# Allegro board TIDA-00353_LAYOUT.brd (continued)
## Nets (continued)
N17161357: C222.1 U10.1(BYPASS)
N17161563: C233.1 C234.1 R177.2 R180.1 U11.5(OUT) Z11.1 Z12.1 Z13.1
N17161629: R175.2 R176.1 U11.8(S\D\)
N17161669: C233.2 R177.1 R178.1 U11.6(ADJ)
N17161679: C232.1 U11.1(BYPASS)
N17161879: C204.1 C205.1 R162.2 U8.5(OUT) Z4.1 Z6.1
N17161936: C200.2 R160.2 R161.2 R235.2 U8.8(S\D\)
N17162041: C214.1 C215.1 R166.2 U9.5(OUT) Z7.1
N17162051: C210.2 R164.2 R165.2 R236.2 U9.8(S\D\)
N17162120: C215.2 R166.1 R167.1 U9.6(ADJ)
N17162132: C213.1 U9.1(BYPASS)
N17162350: C205.2 R162.1 R163.1 U8.6(ADJ)
N17162360: C203.1 U8.1(BYPASS)
N17167261: LMKSPI.2(E) R147.2
N17167267: LMKSPI.4(F) R149.2
N17167273: LMKSPI.8(H) R151.2
N17204057: C162.1 R103.2 Y3.1(VTUNE)
N17204061: C160.1 C161.1 R103.1 U13.32(CPOUT1)
N17204110: REFCLK.1(CENTER) T5.1
N17204122: C149.1 U13.12(LDOBYP2)
N17204150: R110.2 Y1.4(RF) Y2.3(OUT)
N17204206: C148.1 U13.11(LDOBYP1)
N17204360: EXTREF.1(CENTER) R107.2 R108.1
N17204562: C150.1 C151.1 U13.46(CPOUT2)
N17204592: C150.2 R100.1
N17204632: R102.2 Y3.4(RF)
N17204638: C158.2 R101.2 R102.1
N17204674: C168.1 R111.2 R112.1 Y1.1(VTUNE) Y2.1(EN)
N17204744: C152.1 U13.44(OSCIN*)
N17243114: FMC.H37 R65.1
N17243121: FMC.H38 R66.1
N17243521: FMC.G36 R63.2
N17243524: FMC.G37 R64.2
N17262131: BP2.5.1 C96.1 C97.2 C98.1 U12.41(BP2.5_41)
N17267182: C147.2 R96.2 R97.2 R99.1 U13.6(SYNC)
N17394464: Q4.3(D) SYNC.2(CATHODE)
N17403168: OVRA/TRIGRDY.1(ANODE) R58.1
N17405429: OVRB/TRIGGER.1(ANODE) R57.1
N17407540: Q2.1(G) R53.1 R56.2 U12.44(OVRA/TRIGRDY)
N17407548: Q3.1(G) R54.1 R55.2 U12.43(OVRB/TRIGGER)
N17461045: STATUS_LD2.1 U13.48(STATUS_LD2)
N17467440: C153.2 C155.2 C157.2 C158.1 C159.2
N17467450: C153.1 U13.43(OSCIN)
N17467802: C156.1 U13.35(CLKIN1*/FIN*/FBCLKIN*)
N17467807: C157.1 U13.34(CLKIN1/FIN/FBCLKIN)
N17467978: C154.1 U13.38(CLKIN0*)
N17467983: C155.1 U13.37(CLKIN0)
N17471425: STATUS_LD1.1 U13.31(STATUS_LD1)
N17477944: CLKIN_SEL1.1 U13.59(CLKIN_SEL1)
N17492975: C146.2 R94.2 R95.2 R98.1 U13.5(RESET)
N17497915: LMK_RESET.2 R94.1
N17498425: LMK_SYNC.2 R97.1
N17498929: FMC.H31 Q4.1(G) R67.1
N17500015: FMC.D31 R62.1
N17500071: FMC.D30 R62.2
N17502672: R168.2 R169.1 U10.8(S\D\)
N17525558: CLKIN_SEL0.1 U13.58(CLKIN_SEL0)
N17567551: C113.2 R51.2 R52.1 SYSREF_SW.2
N17588026: L1.1 R36.2 U3.24(OPA+)
N17588195: C21.2 T9.3
N17588197: C20.2 T9.1
N17588243: R34.2 U3.22(ENA)
N17588312: R30.1 R31.1 U3.4(MOD0)
N17588326: R32.1 R33.1 U3.5(MOD1)
N17588682: C21.1 U3.30(IPA+)
N17588716: C20.1 U3.29(IPA-)
N17588832: L2.1 R37.2 U3.23(OPA-)
N17588912: L4.2 R38.2 U3.18(OPB-)
N17589096: C22.1 U3.11(IPB+)
N17589248: C23.1 U3.12(IPB-)
N17589348: R35.2 U3.19(ENB)
N17589483: C23.2 T8.3
N17591143: L3.2 R39.2 U3.17(OPB+)
N17597838: R119.1 R120.2 Z1.3
N17597840: C183.1 R119.2 U6.20(VCC)
N17597844: C180.1 R120.1 U7.4(EN) U7.6(VIN)
N17597872: C181.1 U7.1(VOUT) Z3.1
N17597980: R126.1 U6.1(D0)
N17597982: R127.1 U6.5(D1)
N17597984: R128.1 U6.3(D2)
N17597986: R129.1 U6.11(D3)
N17597988: R130.1 U6.2(D4)
N17597998: R131.1 U6.9(D5)
N17598000: R132.1 U6.10(D6)
N17598002: R133.1 U6.6(D7)
N17599264: C185.1 U6.16(USBDM) USB.2(D-)
N17599267: C186.1 U6.15(USBDP) USB.3(D+)
N17600241: USB.1(VBUS) Z1.1
N17600317: C187.1 U6.17(3V3OUT)
N17600450: R121.1 U6.12(P\W\R\E\N\)
N17601684: R134.1 U14.3(A1)
N17602039: R138.1 U15.3(A1)
N17602344: R141.1 U16.3(A1)
N17602346: R142.1 U16.4(A2)
N17602348: R143.1 U16.5(A3)
N17602350: R144.1 U16.6(A4)
N17603643: R135.1 U14.4(A2)
N17603676: R136.1 U14.5(A3)
N17603709: R137.1 U14.6(A4)
N17603775: R139.1 U15.4(A2)
N17603808: R140.1 U15.5(A3)
N17607444: JP2.2 R159.1 U16.9(OEB)
N17608737: J1.4 R17.2 U3.31(A1/SDO/S0A)
N17692169: C2.2 T2.4
N17692215: R2.1 T1.4 VINA-.1(CENTER)
N17692227: C1.1 T1.1
N17692229: C2.1 T1.3
N17692231: R1.2 R3.1 T1.6 VINA+.1(CENTER)
N17692255: R5.2 R6.2 T7.4 VINB+.1(CENTER)
N17692293: C5.2 T6.4
N17692319: C6.1 T7.2
N17692331: C4.2 T6.6
N17692399: C1.2 T2.6
N17692405: C9.1 C10.1 R7.2 R10.2 R11.2 R16.1 VCMA.1
N17692416: R8.1 R10.1 R12.2 R14.1
N17692426: C7.1 R7.1 T2.2
N17692454: R4.2 T7.6 VINB-.1(CENTER)
N17692538: C11.1 C12.1 R22.2 R23.2 R26.2 R27.1 VCMB.1
N17692596: C5.1 T7.3
N17692598: C4.1 T7.1
N17692610: R9.1 R11.1 R13.2 R15.1
N17692612: C8.1 R26.1 T6.2
N17692676: C3.1 T1.2
N17695733: C40.1 L6.1
N17695767: C41.1 L7.1
N17701277: C22.2 T8.1
N17703127: R20.1 R22.1 R24.2 R28.2
N17703165: R21.1 R23.1 R25.2 R29.2
N17704949: C46.1 L10.1
N17704975: C47.1 L11.1
N17708763: R73.1 T3.3
N17708767: R72.1 T3.1
N17709160: R78.1 T4.1
N17709162: R79.1 T4.3
N17709444: CLK.1(CENTER) R70.1 R220.1
N17709615: R71.1 SYSREF.1(CENTER) T4.6
N17746469: C28.2 R36.1
N17746475: C29.2 R37.1
N17746481: C30.2 R38.1
N17746487: C31.2 R39.1
N17748434: R181.2 UNK+5V.1 Z17.1
N17896945: LMKSPI.6(G) R145.1
N17897426: LMKSPI.9(I) R40.2
N17899231: LMKSPI.7(D) R152.1
N17899957: LMKSPI.1(A) R156.1
N17947980: C195.2 JP1.2(PIN2) U14.16(VCCA)
N18004813: R217.2 R219.2 R221.2
N18004844: R220.2 R221.1 T3.6
N18006132: C120.2 T3.2 T3.5
N18006814: C121.2 T4.2 T4.5
N172049681: C161.2 R104.1
N173478561: OVRA/TRIGRDY.2(CATHODE) Q2.3(D)
N173944760: R68.2 SYNC.1(ANODE)
N174054101: OVRB/TRIGGER.2(CATHODE) Q3.3(D)

Pads without a net: FMC A14 A15 A18 A19 A22 A23 A26 A27 A30 A31 A34 A35 A38 A39 B1 B4 B5 B8 B9 B12 B13 B16 B17 B20 B21 B24 B25 B28 B29 B32 B33 B36 B37 B40 C2 C3 C10 C11 C14 C15 C18 C19 C22 C23 C26 C27 C30 C31 C34 C35 C37 C39 D14 D15 D17 D18 D20 D21 D23 D24 D27 D29 D32 D33 D34 D35 D36 D38 D40 E2 E3 E6 E7 E9 E10 E12 E13 E15 E16 E18 E19 E21 E22 E24 E25 E27 E28 E30 E31 E33 E34 E36 E37 F4 F5 F7 F8 F10 F11 F13 F14 F16 F17 F19 F20 F22 F23 F25 F26 F28 F29 F31 F32 F34 F35 F37 F38 G2 G3 G15 G16 G18 G19 G21 G22 G24 G25 G28 G30 G31 G33 G34 H1 H4 H5 H7 H8 H10 H11 H13 H14 H16 H17 H19 H20 H22 H23 H25 H26 H28 H29 H32 H34 H35 J2 J3 J6 J7 J9 J10 J12 J13 J15 J16 J18 J19 J21 J22 J24 J25 J27 J28 J30 J31 J33 J34 J36 J37 K1 K4 K5 K7 K8 K10 K11 K13 K14 K16 K17 K19 K20 K22 K23 K25 K26 K28 K29 K31 K32 K34 K35 K37 K38; LMKSPI 3 5 10; MT1 1; MT2 1; MT3 1; MT4 1; MT5 1; MT6 1; T1 5; T2 5; T6 5; T7 5; T8 5; T9 5; U6 8 13 14 19 22 23 24 27 28; U7 2 5; U8 2 7; U9 2 7; U10 2 7; U11 2 7; U13 1 2 3 4 7 8 9 22 23 27 28 29 30 40 41 49 50 60 61 62 63; U15 6; USB 4; Y1 2 5; Y3 2 5

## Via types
v1: diameter 0.406, hole 0.305, TOP to BOTTOM, 934 vias
v2: diameter 0.559, hole 0.305, TOP to BOTTOM, 1408 vias
v3: diameter 0.508, hole 0.203, TOP to BOTTOM, 46 vias

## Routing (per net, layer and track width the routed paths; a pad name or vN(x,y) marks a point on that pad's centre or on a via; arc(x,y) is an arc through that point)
+4V: length 36
  TOP w0.254: U9.4 v1(29.82,34.35) C212.1 ; U10.4 v1(29.44,47.43) v1(28.43,47.43)
  TOP w0.305: U11.4 v1(101.31,17.4) C231.1 ; C202.1 U8.4
  TOP w0.559: 99.19,11.1 98.68,11.1 ; 99.19,11.1 v2(99.19,11.45) v2(98.17,11.45) v2(98.17,10.75) v2(99.19,10.75) 99.19,11.1 ; 38.28,52.38 38.28,52.21 ; 38.28,52.38 v2(37.92,52.38) v2(37.92,51.7) v2(38.63,51.7) v2(38.63,52.38) 38.28,52.38
  TOP w0.762: 38.28,52.21 R179.2 ; 98.68,11.1 R180.2
  TOP w1.27: C230.1 C231.1 ; C211.1 C212.1 ; C220.1 C221.1
  BOTTOM w0.203: v1(101.31,17.4) 104.45,17.4 105.33,16.52 v1(105.33,14.27)
  BOTTOM w0.559: 7.62,32.61 7.62,32.11 ; 7.62,32.11 v2(7.97,32.11) v2(7.97,33.12) v2(7.27,33.12) v2(7.27,32.11) 7.62,32.11
  BOTTOM w0.762: R181.1 7.62,32.61
  vias: v1(25.27,47.43) v1(25.27,46.53) v1(25.65,34.8) v1(25.65,33.9) v1(25.84,47.43) v1(25.84,46.53) v1(26.22,34.8) v1(26.22,33.9) v1(27.76,47.43) v1(27.76,46.53) v1(28.14,34.8) v1(28.14,33.9) v1(28.43,46.53) v1(28.81,34.8) v1(28.81,33.9) v1(32.45,51.44) v1(32.82,38.1) v1(75.89,106.38) v1(75.89,105.16) v1(76.59,106.38) v1(76.59,105.16) v1(80.47,101.42) v1(100.83,21.54) v1(100.83,20.83) v1(100.96,19.26) v1(100.96,18.04) v1(101.67,19.26) v1(101.67,18.04) v1(101.8,21.54) v1(101.8,20.83)
GND: length 300.9
  TOP w0.203: v1(63.23,66.93) 63.23,68 U12.22 ; U12.40 67.77,73.94 v1(67.8,73.91) ; C90.1 70.31,67.82 v1(70.49,68) ; v1(118.34,91.06) 118.55,91.26 118.85,91.26 ; U12.16 v1(60.22,66.93) ; C112.2 65.06,64.34 v2(65.08,64.36) ; C6.2 v1(19.58,58.31) ; C3.2 v1(19.58,85.08)
  TOP w0.254: U11.3 102.11,14.92 v2(102.51,14.92) ; U8.3 77.04,102.04 v2(77.44,102.04) ; U10.3 31.42,48.23 v2(31.82,48.63) ; U9.3 31.8,35.15 v2(32.2,35.55)
  TOP w0.305: U12.12 v1(58.04,69.44) ; U12.46 v1(64.72,76.58) 64.72,77.27 C62.2 ; U12.9 v1(58.15,70.94) ; U12.6 v1(58.15,72.44) ; U12.3 v1(58.18,73.94) ; U12.49 63.22,76.83 63.58,77.19 C65.2 ; U12.31 v1(67.95,69.44) ; U12.52 v1(61.72,76.45) 61.72,76.87 61.47,77.11 C69.2 ; U12.19 v1(61.72,66.93) ; U12.55 v1(60.22,76.7) 60.41,76.89 C67.2 ; U12.25 v1(64.72,66.96)
  TOP w0.33: C88.2 64.92,66.76 v1(64.72,66.96) ; C82.2 60.19,66.9 v1(60.22,66.93)
  TOP w0.381: v1(64.88,79.12) 64.62,78.87 C61.2 64.62,78.11 v1(64.88,77.85) 64.65,77.62 C62.2 ; R67.2 106.56,60.94 v2(106.35,60.73) ; C67.2 60.41,77.62 v1(60.18,77.85) 60.43,78.11 C66.2 60.43,78.87 v1(60.18,79.12) ; v1(58.04,69.44) 57.94,69.34 C77.1 ; R5.1 R4.1 ; v1(68.97,69.32) C93.2 68.08,69.32 v1(67.95,69.44) ; v1(58.15,70.94) 58.12,70.97 C74.1 ; C154.2 v2(91.14,44) ; C152.2 v2(91.14,47) ; v2(75.09,39.88) R92.1 R93.1 v2(75.09,42.11) R90.1 R91.1 v2(75.09,44.35) ; C96.2 v1(70.21,74.42) ; v1(70.08,75.18) C94.1 ; C80.2 61.8,66.85 v1(61.72,66.93) ; C85.2 63.15,66.85 v1(63.23,66.93) ; v1(63.86,79.12) C64.2 v1(63.86,77.85) 63.58,77.57 C65.2 ; v1(58.15,72.44) 58.12,72.42 C73.1 ; C71.2 57.89,74.04 57.99,73.94 v1(58.18,73.94) ; C117.2 v1(56.04,67.56) ; v1(56.14,75.95) C114.2 ; C69.2 61.47,77.6 v1(61.19,77.88) C68.2 v1(61.19,79.12) ; C156.2 v2(91.14,42.5)
  TOP w0.406: C92.2 v1(71.36,68.95) ; R4.1 v2(11.51,58.7) ; R5.1 v2(11.51,57.91) ; v2(11.51,85.47) R1.1 R2.2 v2(11.51,84.69)
  TOP w0.508: v2(105.14,101.09) R60.2 ; v2(9.34,72.66) 9.54,72.46 R32.2 ; R31.2 9.54,70.93 v2(9.34,70.73)
  TOP w0.559: C169.2 v2(95.76,57.62)
  BOTTOM w0.203: U15.11 23.08,30.77 v2(23.73,30.12) ; U14.7 v2(55.35,26.23) ; U14.1 v2(55.35,30.13) 54.7,29.48 U14.2 ; v1(64.72,76.58) 65.33,76.58 C60.1 ; U15.9 24.38,30.77 v2(23.73,30.12) ; v2(23.73,30.12) U15.10 v2(23.73,32.61) ; C75.1 58.15,70.99 v1(58.15,70.94) 57.84,70.64 C76.1 ; U16.2 54.65,23.03 v2(55.3,23.68) U16.1 ; U14.9 47.56,25.58 v2(46.91,26.23) U14.10 ; U15.7 v2(23.73,38.56) 24.03,38.56 24.38,38.21 U15.8 ; U15.2 20.48,38.12 20.04,38.56 v2(19.83,38.56) U15.1 ; C89.1 67.19,66.9 v1(67.16,66.88) ; U16.10 v2(49.35,19.78) ; v2(54.05,18.47) U16.8 ; C63.1 62.39,76.45 v1(61.72,76.45)
  BOTTOM w0.254: U3.15 15.49,74.48 v1(15.74,74.73) 15.99,74.47 15.99,74.1 U3.16 ; U3.20 17.27,71.94 v2(17.52,71.69) 17.27,71.44 U3.21 ; U3.10 12.99,75.59 v2(12.79,75.78) ; U3.25 15.99,69.29 15.99,68.91 v1(15.74,68.66) 15.49,68.91 U3.26 ; v1(14.56,75.67) 14.49,75.61 U3.13 ; U3.3 9.55,70.94 v2(9.34,70.73) ; U3.7 10.35,72.94 v2(10.15,73.14) ; v2(9.34,72.66) 9.55,72.44 U3.6 ; v2(12.31,74.97) 12.49,74.79 U3.9 ; v2(10.97,73.62) 11.15,73.44 U3.8 ; v1(14.56,67.71) 14.49,67.78 U3.28
  BOTTOM w0.33: v1(60.22,66.93) 60.19,66.9 C79.2 ; C86.1 64.9,66.38 C87.2 64.89,66.79 v1(64.72,66.96)
  BOTTOM w0.381: FMC.J8 v1(113.26,89.79) ; FMC.H33 v1(114.53,58.04) ; FMC.F39 v1(117.07,50.42) ; FMC.G35 v1(115.8,55.5) ; FMC.E23 v1(118.34,70.74) ; FMC.H21 v1(114.53,73.28) ; FMC.A29 v1(123.42,63.12) ; FMC.D28 v1(119.61,64.39) ; FMC.J40 v1(113.26,47.88) ; FMC.F24 v1(117.07,69.47) ; FMC.C40 v1(120.88,49.15) ; FMC.J20 v1(113.26,73.28) ; FMC.A13 v1(123.42,82.17) ; FMC.A4 v1(124.69,93.6) ; FMC.K15 v1(113.26,80.9) ; FMC.G29 v1(115.8,63.12) ; FMC.H12 v1(114.53,83.44) ; FMC.E35 v1(118.34,55.5) ; FMC.D19 v1(119.61,75.82) ; FMC.B23 v1(122.15,70.74) ; FMC.D2 v1(120.88,96.14) ; FMC.C16 v1(122.15,78.36) ; C70.2 58.08,74.04 v1(58.18,73.94) ; v1(63.23,66.93) 62.94,66.64 C84.2 ; FMC.B31 v1(122.15,60.58) ; FMC.A37 v1(123.42,52.96) ; v1(61.72,66.93) 61.44,66.64 C81.2 ; FMC.A1 v1(123.42,98.68) ; FMC.C29 v1(120.88,63.12) ; FMC.C9 v1(122.15,88.52) FMC.C8 v1(122.15,89.79) FMC.B7 ; FMC.E17 v1(118.34,78.36) ; FMC.E40 v1(118.34,47.88) ; FMC.H27 v1(114.53,65.66) ; FMC.G38 v1(115.8,50.42) ; C95.1 v1(70.08,75.18) ; FMC.D3 v1(119.61,96.14) ; FMC.E1 v1(118.34,98.68) ; FMC.K9 v1(113.26,87.25) ; v1(114.53,87.25) FMC.H9 FMC.G8 ; FMC.J1 v1(113.26,98.68) ; FMC.F21 v1(117.07,73.28) ; FMC.A36 v1(123.42,54.23) ; v1(118.34,87.25) FMC.F9 FMC.E8 ; FMC.D6 120.05,91.69 v1(119.41,91.06) 120.05,90.42 FMC.D7 ; FMC.B34 v1(122.15,56.77) ; FMC.K24 v1(111.99,69.47) ; FMC.G11 v1(115.8,85.98) ; FMC.D13 v1(120.88,83.44) FMC.C13 ; C72.1 58.12,72.42 v1(58.15,72.44) ; FMC.A17 v1(123.42,78.36) ; FMC.J29 v1(113.26,63.12) ; FMC.G23 v1(115.8,70.74) ; FMC.K36 v1(111.99,54.23) ; FMC.E20 v1(118.34,73.28) ; FMC.B2 v1(122.15,96.14) FMC.B3 ; FMC.G17 v1(115.8,78.36) ; FMC.A5 v1(123.42,93.6) ; FMC.C28 v1(120.88,64.39) ; FMC.K18 v1(113.26,75.82) ; v1(58.04,69.44) 57.94,69.34 C78.1 ; FMC.H18 v1(115.8,75.82) ; FMC.D10 v1(120.88,85.98) ; FMC.D16 v1(119.61,78.36) ; FMC.J5 v1(113.26,93.6) ; FMC.B6 v1(122.15,91.06) ; FMC.F3 v1(117.07,96.14) ; FMC.K33 v1(111.99,58.04) ; FMC.H6 v1(114.53,92.33) ; FMC.B14 v1(122.15,82.17) ; FMC.C25 v1(120.88,68.2) ; FMC.B15 v1(123.42,80.9) ; FMC.K21 v1(111.99,73.28) ; FMC.A32 v1(123.42,59.31) ; v1(30.84,77.38) v1(30.84,78.27) ; FMC.A24 v1(123.42,69.47) ; FMC.E4 v1(118.34,94.87) ; FMC.B39 v1(122.15,50.42) ; FMC.J11 v1(113.26,85.98) ; FMC.H15 v1(114.53,80.9) FMC.J14 ; FMC.K30 v1(111.99,61.85) ; FMC.K12 v1(113.26,83.44) ; FMC.H36 v1(114.53,54.23) ; FMC.D37 v1(119.61,52.96) ; FMC.C4 v1(122.15,93.6) FMC.C5 ; FMC.C33 v1(120.88,58.04) ; FMC.C32 v1(120.88,59.31) ; FMC.C1 v1(120.88,98.68) ; FMC.K3 v1(111.99,96.14) ; FMC.B27 v1(122.15,65.66) ; FMC.F36 v1(117.07,54.23) ; FMC.E14 v1(118.34,82.17) ; FMC.F15 v1(118.34,80.9) ; FMC.K2 v1(113.26,96.14) ; FMC.D22 v1(119.61,72.01) ; FMC.B19 v1(122.15,75.82) ; FMC.H2 v1(115.8,96.14) ; FMC.C20 v1(120.88,73.28) ; FMC.C12 v1(122.15,83.44) ; FMC.B22 v1(122.15,72.01) ; FMC.J23 v1(113.26,70.74) ; FMC.B26 v1(122.15,66.93) ; FMC.A16 v1(124.69,78.36) ; FMC.H30 v1(114.53,61.85) ; FMC.B11 v1(122.15,85.98) FMC.B10 ; FMC.H39 v1(114.53,49.15) ; FMC.E5 v1(118.34,93.6) ; FMC.G32 v1(115.8,59.31) ; FMC.K27 v1(111.99,65.66) ; FMC.B35 v1(122.15,55.5) ; FMC.E29 v1(118.34,63.12) ; FMC.G14 v1(117.07,80.9) ; FMC.A40 v1(123.42,49.15) ; FMC.A9 v1(124.69,88.52) FMC.A8 ; FMC.A25 v1(123.42,68.2) ; FMC.B30 v1(122.15,61.85) ; FMC.F2 v1(118.34,96.14) ; FMC.G5 v1(115.8,93.6) ; FMC.J38 v1(113.26,50.42) ; FMC.F27 v1(117.07,65.66) ; FMC.A21 v1(124.69,73.28) ; FMC.F33 v1(117.07,58.04) ; FMC.C24 v1(120.88,69.47) ; FMC.G20 v1(115.8,73.28) ; FMC.E32 v1(118.34,59.31) ; FMC.K6 v1(111.99,92.33) ; FMC.F6 v1(118.34,91.06) ; FMC.G40 v1(117.07,47.88) ; FMC.H24 v1(114.53,69.47) ; FMC.F30 v1(117.07,61.85) ; FMC.A20 v1(123.42,73.28) ; FMC.C21 v1(122.15,73.28) ; FMC.C38 v1(120.88,51.69) ; FMC.K39 v1(111.99,49.15) ; v1(30.84,65.12) v1(30.84,66) ; FMC.A33 v1(123.42,58.04) ; FMC.G4 v1(117.07,93.6) ; FMC.G26 v1(115.8,66.93) ; FMC.J17 v1(113.26,78.36) ; FMC.H3 v1(115.8,94.87) ; FMC.J26 v1(113.26,66.93) ; FMC.B18 v1(123.42,75.82) ; FMC.C36 v1(120.88,54.23) ; FMC.F18 v1(118.34,75.82) ; FMC.D39 v1(119.61,50.42) ; FMC.B38 v1(122.15,51.69) ; FMC.E38 v1(118.34,51.69) ; FMC.A28 v1(123.42,64.39) ; FMC.G1 v1(115.8,98.68) ; v1(118.34,83.44) FMC.F12 FMC.E11 ; FMC.A12 v1(124.69,83.44) ; FMC.C17 v1(120.88,78.36) ; FMC.E26 v1(118.34,66.93) ; FMC.J4 v1(113.26,94.87) ; FMC.D25 v1(119.61,68.2) ; FMC.J32 v1(113.26,59.31) ; FMC.J35 v1(113.26,55.5)
  BOTTOM w0.406: C91.2 68.1,69.6 v1(67.95,69.44) ; v1(17.08,75.35) C27.2 C26.1 v1(17.08,76.24) ; v1(17.08,67.15) C24.1 C25.2 v1(17.08,68.04) ; v1(68.45,77.65) 67.14,78.96 C98.2 ; R34.1 v1(19.7,71.07) ; R35.1 v1(19.7,72.32)
  BOTTOM w0.508: C195.1 v2(44.45,30.4) ; v2(86.71,48.42) 86.83,48.42 C139.2 C137.2 ; C140.2 86.89,46.59 v2(86.71,46.77) ; C143.2 84.87,41.63 v2(85.06,41.82) ; v2(85.06,48.42) 85.16,48.52 C144.2 ; v2(80.19,48.44) 80.04,48.59 C145.2 ; v2(86.71,43.47) 86.89,43.29 C133.2 ; C190.1 v2(44.45,29.49) ; v2(80.1,41.82) 79.92,41.63 C141.2 ; C130.2 79.98,45.24 v2(80.1,45.12) 79.87,44.89 C131.2 ; C132.2 86.89,41.64 v2(86.71,41.82) ; v2(86.71,45.12) C138.2 C136.2 ; C149.2 80,43.36 v2(80.1,43.47) ; C142.2 v2(81.75,41.82) ; v2(36.22,85.88) 35.67,85.33 C9.2 35.67,84.82 v2(35.13,84.28)
  BOTTOM w0.559: v2(86.47,12.85) 85.48,12.85 ; 85.48,12.85 v2(84.49,12.85) ; 85.48,12.85 C235.2 85.48,14.06 ; v2(97.04,14.83) 96.05,14.83 ; 96.05,14.83 v2(95.06,14.83) ; 96.05,14.83 C237.2 96.05,16.04 ; 104.86,27.17 v2(103.87,27.17) ; 104.86,27.17 C239.2 104.86,25.95 ; 104.86,27.17 v2(105.85,27.17) ; 96.05,16.04 v2(95.06,16.04) ; 96.05,16.04 v2(97.04,16.04) ; v2(86.47,14.06) 85.48,14.06 ; 85.48,14.06 v2(84.49,14.06) ; 104.86,25.95 v2(105.85,25.95) ; 104.86,25.95 v2(103.87,25.95) ; C191.1 v1(19.62,32.63) ; v2(25.96,73.75) L4.1 ; v2(25.96,81.9) L3.1 ; v2(25.96,69.64) L2.2 ; v2(25.96,61.48) L1.2
  vias: v1(0.34,96.37) v1(0.34,94.74) v1(0.34,87.86) v1(0.34,86.24) v1(0.34,83.92) v1(0.34,82.3) v1(0.34,75.42) v1(0.34,73.79) v1(0.34,69.6) v1(0.34,67.97) v1(0.34,61.09) v1(0.34,59.46) v1(0.34,57.15) v1(0.34,55.53) v1(0.34,48.64) v1(0.34,47.02) v1(2.8,96.37) v1(2.8,94.74) v1(2.8,87.86) v1(2.8,86.24) v1(2.8,83.92) v1(2.8,82.3) v1(2.8,75.42) v1(2.8,73.79) v1(2.8,69.6) v1(2.8,67.97) v1(2.8,61.09) v1(2.8,59.46) v1(2.8,57.15) v1(2.8,55.53) v1(2.8,48.64) v1(2.8,47.02) v1(5.26,96.37) v1(5.26,94.74) v1(5.26,92.03) v1(5.26,90.58) v1(5.26,87.86) v1(5.26,86.24) v1(5.26,83.92) v1(5.26,82.3) v1(5.26,79.58) v1(5.26,78.13) v1(5.26,75.42) v1(5.26,73.79) v1(5.26,69.6) v1(5.26,67.97) v1(5.26,65.26) v1(5.26,63.81) v1(5.26,61.09) v1(5.26,59.46) v1(5.26,57.15) v1(5.26,55.53) v1(5.26,52.81) v1(5.26,51.36) v1(5.26,48.64) v1(5.26,47.02) v1(6.53,92.03) v1(6.53,90.25) v1(6.53,79.91) v1(6.53,78.13) v1(6.53,65.26) v1(6.53,63.47) v1(6.53,53.14) v1(6.53,51.36) v1(7.47,89.31) v1(7.47,80.85) v1(7.47,62.53) v1(7.47,54.08) v1(7.75,87.62) v1(7.75,85.08) v1(7.75,82.54) v1(7.75,60.85) v1(7.75,58.31) v1(7.75,55.77) v1(7.8,91.01) v1(7.8,79.15) v1(7.8,64.24) v1(7.8,52.38) v1(8.41,88.37) v1(8.41,81.79) v1(8.41,55.02) v1(8.74,90.07) v1(8.74,80.09) v1(9.35,87.43) v1(9.35,82.73) v1(9.48,68.48) v1(9.5,63.86) v1(9.68,89.13) v1(9.68,81.03) v1(9.68,62.36) v1(9.68,54.26) v1(10.29,86.49) v1(10.29,85.08) v1(10.29,83.67) v1(10.29,59.72) v1(10.29,58.31) v1(10.29,56.9) v1(10.62,88.19) v1(10.62,81.97) v1(10.62,61.42) v1(10.62,55.2) v1(10.83,67.77) v1(10.83,64.59) v1(11.56,87.25) v1(11.56,82.91) v1(11.56,56.14) v1(12.22,66.22) v1(12.22,61.14) v1(12.53,62.69) v1(12.58,82.14) v1(12.91,80.14) v1(12.91,78.87) v1(12.91,77.6) v1(12.94,72.99) v1(12.94,72.34) v1(12.94,71.69) v1(12.94,71.05) v1(12.94,70.4) v1(12.86,65.58) v1(12.91,64.44) v1(12.93,52.86) v1(13.59,72.99) v1(13.59,72.34) v1(13.59,71.69) v1(13.59,71.05) v1(13.59,70.4) v1(13.74,83.09) v1(13.74,60.3) v1(14.24,72.99) v1(14.24,72.34) v1(14.24,71.69) v1(14.24,71.05) v1(14.24,70.4) v1(14.56,80.14) v1(14.56,78.87) v1(14.56,77.6) v1(14.58,65.71) v1(14.56,63.93) v1(14.91,82.12) v1(14.89,72.99) v1(14.89,72.34) v1(14.89,71.69) v1(14.89,71.05) v1(14.89,70.4) v1(15.01,87.51) v1(15.01,86.88) v1(15.01,86.26) v1(15.01,57.13) v1(15.01,56.5) v1(15.01,55.88) v1(15.07,62.69) v1(15.54,72.99) v1(15.54,72.34) v1(15.54,71.69) v1(15.54,71.05) v1(15.54,70.4) v1(15.47,51.34) v1(17.33,60.43) v1(18.01,51.34) v1(18.99,30) v1(29.97,85.08) v1(29.97,58.31) v1(34.92,78.34) v1(34.92,77.32) v1(34.92,66.07) v1(34.92,65.05) v1(35.18,59.03) v1(36.14,57.58) v1(36.33,62.56) v1(37.6,62.56) v1(38.87,62.56) v1(40.14,62.56) v1(42.61,62.56) v1(42.79,52.5) v1(43.88,62.56) v1(44.67,64.62) v1(44.7,54.38) v1(44.7,52.5) v1(45.33,60.73) v1(45.48,63.8) v1(45.47,55.91) v1(45.75,5.19) v1(45.75,2.73) v1(45.75,0.27) v1(46.35,62.56) v1(46.6,56.31) v1(46.74,24.52) v1(46.76,52.3) v1(46.79,18.68) v1(47.09,17.83) v1(47.38,5.19) v1(47.38,2.73) v1(47.38,0.27) v1(47.67,24.63) v1(47.8,58.93) v1(47.85,57.07) v1(47.87,54.13) v1(48.3,50.9) v1(49.12,59.21) v1(49.1,56.46) v1(49.76,51.33) v1(51.18,74.69) v1(51.18,68.69) v1(52.7,8.26) v1(53.52,55.09) v1(53.77,52.12) v1(54.26,5.19) v1(54.26,2.73) v1(54.26,0.27) v1(55.5,62.89) v1(55.63,8.26) v1(55.89,5.19) v1(55.89,2.73) v1(55.89,0.27) v1(56.26,58.19) v1(57.45,64.9) v1(57.63,5.19) v1(57.63,2.73) v1(57.63,0.27) v1(58.48,62.97) v1(58.86,55.17) v1(59.18,66.22) v1(59.21,63.93) v1(59.2,57.63) v1(59.26,5.19) v1(59.26,2.73) v1(59.26,0.27) v1(59.89,64.59) v1(60.02,62.08) v1(60.04,58.8) v1(60.53,36.77) v1(61.35,85.72) v1(61.37,94.51) v1(61.37,91.16) v1(61.37,89.64) v1(61.37,88.29) v1(61.37,83.31) v1(61.8,63.27) v1(62.48,61.34) v1(62.48,60.07) v1(62.48,58.8) v1(62.48,55.14) v1(62.48,53.87) v1(62.56,64.77) v1(64.04,88.29) v1(64.04,86.54) v1(65.18,55.14) v1(65.18,53.87) v1(65.77,51.99) v1(66.02,49.12) v1(66.02,47.73) v1(66.14,5.19) v1(66.14,2.73) v1(66.14,0.27) v1(66.58,88.98) v1(67.03,17.53) v1(67.21,86.44) v1(67.53,35.56) v1(67.65,64.16) v1(67.65,62.89) v1(67.65,61.62) v1(67.61,60.5) v1(67.77,5.19) v1(67.77,2.73) v1(67.77,0.27) v1(68.35,59.03) v1(68.48,88.98) v1(68.48,86.44) v1(68.51,81.76) v1(68.51,76.78) v1(69.12,58.24) v1(69.05,36.77) v1(69.55,60.35) v1(69.82,17.53) v1(70.06,57.3) v1(71.28,86.44) v1(71.28,83.9) v1(71.6,17.53) v1(72.34,56.72) v1(72.49,18.41) v1(72.7,68) v1(73,66.17) v1(73.44,60.68) v1(73.38,17.53) v1(73.82,86.44) v1(73.82,83.9) v1(73.84,54.89) v1(74.15,81.69) v1(74.15,79.15) v1(74.05,5.19) v1(74.05,2.73) v1(74.05,0.27) v1(74.88,59.26) v1(75.11,54.89) v1(75.42,81.69) v1(75.42,80.42) v1(75.52,56.72) v1(75.68,5.19) v1(75.68,2.73) v1(75.68,0.27) v1(76.36,86.44) v1(76.36,83.9) v1(76.38,54.89) v1(76.43,17.53) v1(76.69,81.69) v1(76.79,56.72) v1(77.06,11.66) v1(78.16,57.39) v1(78.36,55.08) v1(78.61,40.64) v1(78.9,85.8) v1(78.9,83.9) v1(79.1,58.33) v1(79.3,56.02) v1(80.04,59.27) v1(80.24,56.96) v1(80.62,89.74) v1(80.75,85.04) v1(80.98,60.21) v1(81.18,57.9) v1(81.92,61.15) v1(82.12,58.84) v1(82.45,54.31) v1(82.56,5.19) v1(82.56,2.73) v1(82.56,0.27) v1(82.86,62.09) v1(82.99,57.23) v1(83.06,59.78) v1(83.46,51.97) v1(83.8,63.03) v1(83.85,75.9) v1(83.93,58.17) v1(84,60.72) v1(84.19,5.19) v1(84.19,2.73) v1(84.19,0.27) v1(84.31,68.38) v1(84.61,74.02) v1(84.79,76.83) v1(84.76,64) v1(84.94,61.66) v1(84.87,59.11) v1(84.94,56.29) v1(85.25,69.32) v1(85.55,74.96) v1(85.73,77.77) v1(85.66,55.14) v1(85.66,53.75) v1(85.66,52.35) v1(85.81,60.05) v1(85.88,62.6) v1(85.88,57.23) v1(86.19,70.26) v1(86.29,73.08) v1(86.49,75.9) v1(86.67,78.71) v1(86.75,60.99) v1(86.77,66) v1(86.82,63.54) v1(86.82,58.17) v1(86.75,5.19) v1(86.75,2.73) v1(86.75,0.27) v1(86.99,68.38) v1(87.23,74.02) v1(87.43,76.83) v1(87.69,61.93) v1(87.76,59.11) v1(87.83,55.04) v1(87.83,53.64) v1(87.83,52.25) v1(87.93,69.32) v1(88.12,56.29) v1(88.17,74.96) v1(88.37,77.77) v1(88.38,5.19) v1(88.38,2.73) v1(88.38,0.27) v1(88.63,62.87) v1(88.63,34.71) v1(88.65,80.7) v1(88.7,60.05) v1(88.87,70.26) v1(89.01,73.08) v1(89.11,75.9) v1(89.1,68.38) v1(89.06,57.23) v1(89.31,78.71) v1(89.31,66) v1(89.57,63.8) v1(89.64,60.99) v1(89.81,71.2) v1(89.95,74.02) v1(90.05,76.83) v1(90.04,69.32) v1(90,58.17) v1(90.25,66.94) v1(90.43,82.47) v1(90.58,61.93) v1(90.75,72.14) v1(90.89,74.96) v1(90.94,59.11) v1(90.99,77.77) v1(90.98,70.26) v1(91.19,80.59) v1(91.19,67.88) v1(91.37,83.41) v1(91.52,62.87) v1(91.69,73.08) v1(91.83,75.9) v1(91.92,71.2) v1(91.93,66.17) v1(91.88,60.05) v1(92.13,81.53) v1(92.13,68.82) v1(92.33,39.88) v1(92.46,63.8) v1(92.63,74.02) v1(92.77,76.83) v1(92.82,60.99) v1(92.87,79.65) v1(92.86,72.14) v1(92.87,67.11) v1(93.07,82.47) v1(93.07,69.76) v1(93.07,47.25) v1(93.25,85.29) v1(93.57,74.96) v1(93.71,77.77) v1(93.81,80.59) v1(93.8,73.08) v1(93.81,68.05) v1(93.76,61.93) v1(94.01,70.7) v1(94.19,86.23) v1(94.65,78.71) v1(94.74,74.02) v1(94.75,68.99) v1(94.7,62.87) v1(94.82,66.17) v1(94.95,84.35) v1(94.95,71.64) v1(95.13,87.17) v1(95.26,5.19) v1(95.26,2.73) v1(95.26,0.27) v1(95.45,76.83) v1(95.59,79.65) v1(95.64,63.8) v1(95.69,82.47) v1(95.69,69.93) v1(95.76,67.11) v1(95.89,85.29) v1(95.89,72.58) v1(96.07,88.11) v1(96.39,77.77) v1(96.37,75.64) v1(96.63,83.41) v1(96.63,70.87) v1(96.7,68.05) v1(96.83,86.23) v1(96.89,5.19) v1(96.89,2.73) v1(96.89,0.27) v1(97.33,78.71) v1(97.31,76.58) v1(97.46,89.51) v1(97.46,81.53) v1(97.57,84.35) v1(97.57,71.81) v1(97.64,68.99) v1(97.77,87.17) v1(97.77,74.46) v1(98,66.17) v1(98.08,23.79) v1(98.25,77.52) v1(98.26,79.65) v1(98.4,82.47) v1(98.51,85.29) v1(98.58,69.93) v1(98.71,88.11) v1(98.71,75.4) v1(98.94,67.11) v1(99.01,91.06) v1(99.01,73.25) v1(99.2,80.59) v1(99.34,83.41) v1(99.45,86.23) v1(99.88,68.05) v1(99.95,74.19) v1(100.11,89.51) v1(100.14,81.53) v1(100.28,84.35) v1(100.44,92.48) v1(100.39,87.17) v1(100.46,71.81) v1(100.89,75.13) v1(101.08,82.47) v1(101.22,85.29) v1(101.33,88.11) v1(101.4,72.75) v1(101.76,93.8) v1(101.76,69.93) v1(102.02,83.41) v1(102.11,80.9) v1(102.16,86.23) v1(102.34,73.69) v1(102.67,94.72) v1(102.72,89.51) v1(102.7,70.87) v1(103,91.06) v1(102.96,84.35) v1(103.08,92.48) v1(103.1,87.17) v1(103.38,80.9) v1(103.59,95.63) v1(103.64,71.81) v1(104.04,88.11) v1(104.12,78.36) v1(104.5,96.55) v1(104.48,75.82) v1(104.65,91.06) v1(104.65,89.79) v1(104.65,80.9) v1(104.91,94.31) v1(104.88,86.28) v1(105.11,73.28) v1(105.42,97.46) v1(105.39,83.13) v1(105.39,78.36) v1(105.75,75.82) v1(105.82,95.22) v1(105.92,91.06) v1(105.92,89.79) v1(105.92,86.56) v1(105.92,80.9) v1(106.38,73.28) v1(106.74,96.14) v1(107.27,98.35) v1(108.64,98.58) v1(109.91,98.58) v1(109.91,96.14) v1(109.91,92.33) v1(109.91,91.06) v1(109.91,89.79) v1(109.91,88.52) v1(109.91,87.25) v1(109.91,85.98) v1(109.91,84.71) v1(109.91,83.44) v1(109.91,80.9) v1(109.91,78.36) v1(109.91,75.82) v1(109.91,73.28) v1(111.18,98.58) v1(111.18,96.14) v1(125.46,97.41) v1(125.46,96.14) v1(125.46,91.06) v1(125.46,89.79) v1(125.46,85.98) v1(125.46,84.71) v1(125.46,73.41) v1(125.61,81.13) v1(125.96,88.49) v1(126.4,74.35) v1(127.13,90.14) v1(127.13,88.87) v1(127.16,87.83) v1(127.34,75.29) v1(128.28,76.23) v1(129.21,77.17) v1(130.15,78.11) v1(131.04,79.04) v2(2.28,44.45) v2(2.28,41.91) v2(2.28,39.37) v2(2.28,36.83) v2(2.28,34.29) v2(2.28,31.75) v2(2.28,29.21) v2(2.28,26.67) v2(2.28,24.13) v2(3.97,25.45) v2(3.97,24.23) v2(4.45,27.61) v2(4.45,26.9) v2(4.82,44.45) v2(4.82,41.91) v2(4.82,39.37) v2(4.82,36.83) v2(4.82,34.29) v2(4.82,31.75) v2(4.82,29.21) v2(5.47,27.61) v2(5.47,26.9) v2(5.95,25.45) v2(5.95,24.23) v2(6.46,76.45) v2(6.46,73.91) v2(6.46,71.37) v2(6.46,68.83) v2(6.46,66.29) v2(7.36,44.45) v2(7.36,41.91) v2(7.36,39.37) v2(7.36,29.21) v2(7.36,26.67) v2(7.36,24.13) v2(7.65,47.16) v2(9,104.39) v2(9,101.85) v2(9,99.31) v2(9,96.77) v2(9,94.23) v2(9,91.69) v2(9,78.99) v2(9,76.45) v2(9.27,47.83) v2(9.27,46.61) v2(9.9,39.37) v2(9.9,24.13) v2(10.16,52.75) v2(11.05,47.83) v2(11.05,46.61) v2(11.54,104.39) v2(11.54,99.31) v2(11.54,96.77) v2(11.54,94.23) v2(11.54,91.69) v2(11.54,89.15) v2(11.54,81.53) v2(11.54,78.99) v2(11.54,76.45) v2(12.44,49.53) v2(12.44,46.99) v2(12.44,44.45) v2(12.44,41.91) v2(12.44,39.37) v2(12.44,36.83) v2(12.44,34.29) v2(12.44,31.75) v2(12.44,29.21) v2(12.44,26.67) v2(12.44,24.13) v2(14.08,104.39) v2(14.08,101.85) v2(14.08,99.31) v2(14.08,96.77) v2(14.08,94.23) v2(14.08,91.69) v2(14.08,89.15) v2(14.98,49.53) v2(14.98,46.99) v2(14.98,44.45) v2(14.98,41.91) v2(14.98,39.37) v2(14.98,36.83) v2(14.98,34.29) v2(14.98,31.75) v2(14.98,29.21) v2(14.98,26.67) v2(14.98,24.13) v2(15.34,55.6) v2(15.34,53.06) v2(16.62,104.39) v2(16.62,101.85) v2(16.62,99.31) v2(16.62,96.77) v2(16.62,94.23) v2(16.62,91.69) v2(16.62,89.15) v2(16.62,81.53) v2(16.62,78.99) v2(16.62,65.02) v2(17.25,68.83) v2(17.52,49.53) v2(17.52,46.99) v2(17.52,44.45) v2(17.52,41.91) v2(17.52,39.37) v2(17.52,36.83) v2(17.52,34.29) v2(17.52,31.75) v2(17.52,29.21) v2(17.52,26.67) v2(17.52,24.13) v2(17.88,55.6) v2(17.88,53.06) v2(19.16,104.39) v2(19.16,101.85) v2(19.16,99.31) v2(19.16,96.77) v2(19.16,94.23) v2(19.16,91.69) v2(19.16,89.15) v2(19.16,81.53) v2(19.16,78.99) v2(19.16,76.45) v2(19.16,66.93) v2(19.16,65.02) v2(19.16,62.48) v2(19.79,55.6) v2(20.06,46.99) v2(20.06,44.07) v2(20.06,41.53) v2(20.06,34.29) v2(20.06,24.13) v2(20.42,53.06) v2(21.06,56.87) v2(21.47,105.41) v2(21.7,99.31) v2(21.7,94.23) v2(21.7,91.69) v2(21.7,89.15) v2(21.7,86.61) v2(21.7,84.07) v2(21.7,81.53) v2(21.7,78.99) v2(21.7,73.91) v2(21.7,68.83) v2(21.7,64.39) v2(21.7,62.48) v2(21.7,60.58) v2(22.48,28.07) v2(22.6,34.29) v2(22.6,24.13) v2(22.96,54.97) v2(22.96,53.06) v2(23.23,46.99) v2(23.23,44.07) v2(23.23,41.53) v2(24.24,99.31) v2(24.24,96.77) v2(24.24,94.23) v2(24.24,91.69) v2(24.24,89.15) v2(24.24,81.53) v2(24.24,78.99) v2(24.24,76.45) v2(24.24,73.91) v2(24.24,68.83) v2(24.24,66.93) v2(24.24,64.39) v2(24.24,62.48) v2(24.24,60.58) v2(24.5,34.29) v2(25.14,24.13) v2(25.28,44.89) v2(25.28,44) v2(25.5,55.6) v2(25.46,32.23) v2(25.46,31.34) v2(25.77,41.53) v2(25.86,44.89) v2(25.85,43.99) v2(26.34,31.33) v2(26.35,32.23) v2(26.55,105.41) v2(26.68,101.35) v2(26.67,29.49) v2(26.78,99.31) v2(26.78,96.77) v2(26.78,94.23) v2(26.78,91.69) v2(26.78,89.15) v2(26.78,81.53) v2(26.78,73.91) v2(26.78,71.37) v2(26.78,68.83) v2(26.78,62.48) v2(26.78,60.58) v2(27.68,24.13) v2(27.84,44.57) v2(27.84,43.87) v2(27.92,31.9) v2(27.92,31.21) v2(28.04,55.6) v2(28.04,53.06) v2(28.31,41.53) v2(28.43,44.57) v2(28.42,43.88) v2(28.73,48.81) v2(29.02,31.9) v2(29.01,31.22) v2(29.11,35.73) v2(29.12,24.14) v2(29.21,29.49) v2(29.32,99.31) v2(29.32,96.77) v2(29.32,94.23) v2(29.32,91.69) v2(29.32,89.15) v2(29.32,81.53) v2(29.32,73.91) v2(29.32,71.37) v2(29.32,68.83) v2(29.32,62.48) v2(29.32,60.58) v2(30.58,55.6) v2(30.58,53.06) v2(30.59,45.59) v2(30.59,44.32) v2(30.65,24.14) v2(30.84,49.78) v2(30.84,48.64) v2(30.84,47.5) v2(30.92,32.48) v2(30.92,31.21) v2(31.18,36.69) v2(31.18,35.55) v2(31.18,34.4) v2(31.35,45.59) v2(31.35,44.32) v2(31.63,105.41) v2(31.69,32.48) v2(31.69,31.21) v2(31.75,29.49) v2(31.76,101.35) v2(31.82,49.77) v2(31.82,47.5) v2(31.86,99.31) v2(31.86,96.77) v2(31.86,94.23) v2(31.86,91.69) v2(31.86,86.61) v2(31.86,81.53) v2(31.86,73.91) v2(31.86,71.37) v2(31.86,68.83) v2(31.86,62.48) v2(31.86,60.58) v2(32.2,36.69) v2(32.2,34.4) v2(32.45,52.45) v2(32.54,24.14) v2(32.75,49.78) v2(32.75,48.64) v2(32.75,47.5) v2(32.83,39.8) v2(33.08,38.91) v2(33.18,36.68) v2(33.18,35.53) v2(33.18,34.4) v2(34.29,29.49) v2(34.4,99.31) v2(34.4,96.77) v2(34.4,94.23) v2(34.4,91.69) v2(34.4,89.15) v2(34.4,86.61) v2(34.4,81.53) v2(34.4,73.91) v2(34.4,71.37) v2(34.4,68.83) v2(34.4,62.48) v2(34.43,24.14) v2(34.49,43.43) v2(34.98,40.44) v2(35.66,59.97) v2(35.66,56.87) v2(35.66,54.97) v2(35.66,53.06) v2(35.66,50.52) v2(36.83,29.49) v2(36.94,99.31) v2(36.94,96.77) v2(36.94,94.23) v2(36.94,91.69) v2(36.94,89.15) v2(36.94,86.61) v2(36.86,84.2) v2(36.94,81.53) v2(36.94,78.99) v2(36.94,76.45) v2(36.94,73.91) v2(36.94,71.37) v2(36.94,68.83) v2(36.94,66.93) v2(36.94,64.39) v2(37.19,42.06) v2(37.24,39.52) v2(37.49,38.33) v2(37.49,35.79) v2(37.66,46.78) v2(37.67,43.69) v2(38.04,33.7) v2(38.49,105.41) v2(38.49,102.11) v2(38.84,78.99) v2(38.84,76.45) v2(38.84,73.91) v2(38.84,71.37) v2(38.84,68.83) v2(38.84,66.93) v2(38.84,64.39) v2(38.89,43.69) v2(38.86,40.39) v2(39.12,58.78) v2(39.12,56.87) v2(39.12,54.97) v2(39.12,53.06) v2(39.37,29.49) v2(39.48,99.31) v2(39.48,96.77) v2(39.48,94.23) v2(39.48,91.69) v2(39.48,89.15) v2(39.48,86.61) v2(39.48,84.07) v2(39.48,81.53) v2(40.75,78.99) v2(40.75,76.45) v2(40.75,73.91) v2(40.75,71.37) v2(40.75,68.83) v2(40.75,66.93) v2(40.75,64.39) v2(41.02,58.78) v2(41.02,56.87) v2(41.02,54.97) v2(41.38,86.61) v2(41.38,84.07) v2(41.91,29.49) v2(42.02,99.31) v2(42.02,96.77) v2(42.02,94.23) v2(42.02,91.69) v2(42.04,50.24) v2(42.04,36.88) v2(42.02,32.77) v2(42.02,32) v2(42.14,48.13) v2(42.14,47.24) v2(42.14,43.31) v2(42.14,42.42) v2(42.24,41.1) v2(42.93,58.78) v2(42.93,56.87) v2(43.03,48.13) v2(43.03,47.24) v2(43.03,43.31) v2(43.03,42.42) v2(43.03,32.77) v2(43.03,32) v2(43.49,24.13) v2(43.57,105.41) v2(43.57,102.11) v2(43.79,50.16) v2(43.79,45.34) v2(43.79,34.67) v2(44.56,99.31) v2(44.56,94.23) v2(44.83,58.78) v2(44.78,41.1) v2(44.98,36.22) v2(45.14,22.94) v2(45.14,17.86) v2(45.14,15.32) v2(45.14,12.78) v2(45.14,10.24) v2(45.14,7.7) v2(45.62,46.23) v2(46.46,73.66) v2(46.46,71.75) v2(46.46,69.85) v2(46.69,11) v2(46.69,8.46) v2(46.69,5.92) v2(46.88,16.51) v2(47.1,99.31) v2(47.1,96.77) v2(47.1,94.23) v2(47.1,92.71) v2(47.1,91.19) v2(47.1,89.66) v2(47.1,88.14) v2(47.1,85.6) v2(47.1,83.06) v2(47.1,77.98) v2(47.5,45.26) v2(48.37,71.75) v2(48.65,105.41) v2(48.65,102.11) v2(49.23,11) v2(49.23,8.46) v2(49.23,5.92) v2(49.53,49.58) v2(49.64,99.31) v2(49.64,96.77) v2(49.64,94.23) v2(49.64,92.71) v2(49.64,91.19) v2(49.64,89.66) v2(49.64,88.14) v2(49.64,85.6) v2(49.64,83.06) v2(49.64,80.52) v2(49.58,46.23) v2(49.58,44.4) v2(49.56,39.93) v2(49.76,7.01) v2(50.27,71.75) v2(51.41,72.42) v2(51.41,71.09) v2(51.68,103.87) v2(51.68,102.9) v2(51.74,60.6) v2(51.74,58.37) v2(51.77,23.7) v2(51.77,21.16) v2(51.77,18.62) v2(51.77,16.08) v2(51.77,13.54) v2(51.77,11) v2(52.18,94.23) v2(52.18,92.71) v2(52.18,91.19) v2(52.18,89.66) v2(52.18,88.14) v2(52.18,85.6) v2(52.2,83.19) v2(52.39,103.87) v2(52.39,102.9) v2(52.68,77.22) v2(52.68,66.17) v2(52.86,80.57) v2(53.01,96.22) v2(53.27,99.62) v2(53.79,102.29) v2(53.8,60.6) v2(53.93,97.79) v2(53.95,94.23) v2(53.95,92.71) v2(53.95,91.19) v2(53.95,89.66) v2(54.01,87.5) v2(54.26,75.84) v2(54.34,66.93) v2(54.31,16.08) v2(54.31,13.54) v2(54.31,11) v2(54.31,5.92) v2(54.46,46.74) v2(55.04,103.87) v2(55.04,102.65) v2(55.35,43.51) v2(55.35,40.97) v2(55.35,38.43) v2(55.35,35.89) v2(55.35,33.35) v2(55.58,79.04) v2(55.76,98.22) v2(56.01,94.23) v2(56.01,92.71) v2(56.01,91.19) v2(56.01,89.66) v2(56.01,88.14) v2(56.37,49.28) v2(56.37,46.74) v2(56.67,66.83) v2(56.85,18.62) v2(56.85,16.08) v2(56.85,13.54) v2(56.85,11) v2(56.85,8.46) v2(56.85,5.92) v2(57.02,103.87) v2(57.02,102.65) v2(56.95,99.62) v2(57.1,40.82) v2(57.1,38.28) v2(57.1,35.74) v2(57.1,33.2) v2(57.1,30.66) v2(57.1,28.12) v2(57.1,25.58) v2(57.51,76.58) v2(57.61,83.92) v2(57.61,81.66) v2(57.64,52.07) v2(57.92,86.23) v2(58.17,98.37) v2(58.27,49.28) v2(58.27,46.74) v2(58.27,45.01) v2(58.27,42.47) v2(58.45,101.09) v2(58.87,33.2) v2(58.87,30.66) v2(58.87,28.12) v2(58.87,25.58) v2(59.3,103.87) v2(59.3,102.9) v2(59.45,53.85) v2(59.39,13.54) v2(59.39,11) v2(59.39,8.46) v2(59.39,5.92) v2(59.67,94.23) v2(59.67,92.71) v2(59.67,91.19) v2(59.67,89.64) v2(59.67,87.5) v2(59.67,84.33) v2(59.67,82.42) v2(59.67,80.52) v2(59.72,52.15) v2(59.72,51.03) v2(59.69,20.46) v2(60.01,103.87) v2(60.01,102.9) v2(60.63,45.11) v2(60.63,43.97) v2(61.11,47.34) v2(61.11,46.64) v2(61.11,42.52) v2(61.11,41.81) v2(61.41,102.29) v2(61.63,40.82) v2(61.63,38.28) v2(61.63,35.74) v2(61.63,33.2) v2(61.63,30.66) v2(61.63,28.12) v2(61.63,25.58) v2(61.93,16.08) v2(61.93,13.54) v2(61.93,11) v2(61.93,8.46) v2(61.93,5.92) v2(62.12,47.34) v2(62.12,46.64) v2(62.12,42.52) v2(62.12,41.81) v2(62.61,45.11) v2(62.61,43.97) v2(62.66,103.87) v2(62.66,102.65) v2(62.72,85.22) v2(62.72,51.56) v2(63.78,33.2) v2(63.78,30.66) v2(63.78,28.12) v2(63.78,25.58) v2(64.47,22.28) v2(64.47,18.62) v2(64.47,16.08) v2(64.47,13.54) v2(64.47,11) v2(64.47,8.46) v2(64.47,5.92) v2(64.64,103.87) v2(64.64,102.65) v2(65,57.25) v2(65.71,61.82) v2(65.71,60.55) v2(65.77,85.09) v2(66.12,33.2) v2(66.12,30.66) v2(66.12,28.12) v2(66.12,25.58) v2(66.76,57.89) v2(67.01,22.28) v2(67.01,11) v2(67.01,8.46) v2(67.01,5.92) v2(67.7,56.95) v2(68.13,48.01) v2(68.15,52.91) v2(68.64,56.01) v2(68.61,44.65) v2(68.66,33.2) v2(68.66,25.58) v2(69.4,50.88) v2(69.55,11) v2(69.55,8.46) v2(69.55,5.92) v2(69.88,43.38) v2(70.06,54.81) v2(70.72,103.38) v2(70.72,100.84) v2(70.72,98.3) v2(70.72,95.76) v2(70.72,93.22) v2(70.69,46.74) v2(71.15,44.98) v2(71.2,38.28) v2(71.2,35.74) v2(71.2,33.2) v2(71.2,28.12) v2(71.2,25.58) v2(71.28,42.11) v2(72.12,75.06) v2(72.12,49.56) v2(72.09,11) v2(72.09,8.46) v2(72.09,5.92) v2(72.62,98.93) v2(72.62,96.39) v2(72.62,93.85) v2(72.62,90.93) v2(72.62,89.53) v2(72.62,88.14) v2(72.88,44.15) v2(73.09,106.38) v2(73.09,105.16) v2(73.13,103.29) v2(73.13,102.59) v2(73.19,42.11) v2(73.21,35.92) v2(73.44,53.04) v2(73.74,38.28) v2(73.79,106.38) v2(73.79,105.16) v2(74.17,50.75) v2(74.34,103.29) v2(74.34,102.59) v2(74.38,30.66) v2(74.38,28.12) v2(74.38,25.58) v2(74.63,48.79) v2(74.63,11) v2(74.63,8.46) v2(74.63,5.92) v2(74.88,46.05) v2(75.16,96.39) v2(75.16,93.85) v2(75.16,92.46) v2(75.16,90.93) v2(75.16,89.53) v2(75.16,88.14) v2(75.16,75.06) v2(75.16,72.77) v2(75.16,70.61) v2(75.16,68.33) v2(75.29,65.91) v2(75.29,64.01) v2(75.29,61.47) v2(75.59,97.35) v2(75.62,50.11) v2(75.98,53.04) v2(76.03,38.13) v2(76.19,103.09) v2(76.19,102.04) v2(76.19,101) v2(76.97,36.8) v2(77.25,46.88) v2(77.17,11) v2(77.17,8.46) v2(77.17,5.92) v2(77.32,79.63) v2(77.32,78.74) v2(77.44,103.09) v2(77.44,101) v2(77.62,105.13) v2(77.7,96.39) v2(77.7,93.85) v2(77.7,92.46) v2(77.7,90.93) v2(77.7,89.53) v2(77.7,88.14) v2(77.7,75.18) v2(77.7,72.9) v2(77.7,68.45) v2(77.83,70.61) v2(77.83,66.04) v2(77.98,64.14) v2(77.98,61.59) v2(77.98,59.05) v2(78.52,53.04) v2(78.68,103.09) v2(78.68,102.04) v2(78.68,101) v2(79.71,36.7) v2(79.71,34.85) v2(79.71,31.39) v2(79.71,29.82) v2(79.71,26.24) v2(79.71,23.7) v2(79.71,21.16) v2(79.71,18.62) v2(79.71,16.08) v2(79.71,13.54) v2(79.71,11) v2(79.71,8.46) v2(79.71,5.92) v2(80.24,96.39) v2(80.24,75.06) v2(80.24,72.9) v2(80.24,70.61) v2(80.24,68.33) v2(80.37,65.91) v2(80.52,64.14) v2(80.52,61.59) v2(80.63,85.96) v2(80.59,46.76) v2(80.76,81.26) v2(80.88,98.93) v2(81.51,101.19) v2(81.75,48.42) v2(81.75,46.77) v2(81.75,45.12) v2(81.75,43.47) v2(82.22,38.07) v2(82.22,36.04) v2(82.25,26.24) v2(82.25,23.7) v2(82.25,21.16) v2(82.25,18.62) v2(82.25,16.08) v2(82.25,13.54) v2(82.25,11) v2(82.25,8.46) v2(82.25,5.92) v2(82.4,101.44) v2(82.78,98.93) v2(82.78,96.39) v2(82.86,34.09) v2(82.86,32.13) v2(82.86,29.01) v2(82.86,27.05) v2(83.04,93.85) v2(83.04,92.46) v2(83.04,90.93) v2(83.04,89.53) v2(83.04,88.14) v2(83.06,64.14) v2(83.06,14.6) v2(83.16,75.06) v2(83.16,72.9) v2(83.16,70.61) v2(83.16,68.33) v2(83.16,65.91) v2(83.41,48.42) v2(83.41,46.77) v2(83.41,45.12) v2(83.41,43.47) v2(83.41,41.82) v2(83.95,34.09) v2(83.95,32.13) v2(83.95,29.01) v2(83.95,27.05) v2(84.15,8.46) v2(84.15,5.92) v2(84.58,38.07) v2(84.58,36.04) v2(84.79,26.24) v2(84.79,23.7) v2(84.79,21.16) v2(85.06,46.77) v2(85.06,45.12) v2(85.06,43.47) v2(85.4,29.01) v2(85.4,27.05) v2(85.58,98.93) v2(85.58,96.39) v2(85.58,93.85) v2(85.58,92.46) v2(85.58,90.93) v2(85.58,89.53) v2(85.58,88.14) v2(85.6,38.02) v2(86.06,8.46) v2(86.06,5.92) v2(86.41,34.87) v2(86.49,29.01) v2(86.49,27.05) v2(87.07,31.37) v2(87.07,29.82) v2(87.07,26.11) v2(87.42,38.21) v2(87.42,36.87) v2(88.12,96.39) v2(88.12,93.85) v2(88.12,92.46) v2(88.12,90.93) v2(88.12,89.53) v2(88.12,88.14) v2(88.6,31.32) v2(88.6,28.78) v2(88.6,26.24) v2(88.6,23.7) v2(88.6,21.16) v2(88.6,18.62) v2(88.6,16.08) v2(88.6,13.54) v2(88.6,8.46) v2(88.6,5.92) v2(90.28,87.25) v2(90.66,98.93) v2(90.66,96.39) v2(90.66,93.85) v2(90.66,92.46) v2(90.66,90.93) v2(90.66,89.53) v2(90.66,88.14) v2(91.14,21.16) v2(91.14,18.62) v2(91.14,16.08) v2(91.14,13.54) v2(91.14,8.46) v2(91.14,5.92) v2(91.58,28.83) v2(91.58,26.76) v2(91.58,24.69) v2(92.11,49.44) v2(92.11,48.17) v2(92.39,28.83) v2(92.39,26.76) v2(92.39,24.69) v2(93.2,105.92) v2(93.2,104.01) v2(93.2,101.47) v2(93.2,98.93) v2(93.2,96.39) v2(93.2,93.85) v2(93.2,92.46) v2(93.2,90.93) v2(93.2,89.53) v2(93.2,88.14) v2(93.64,16.58) v2(93.68,21.16) v2(93.68,8.46) v2(93.68,5.92) v2(94.16,58.94) v2(94.16,56.4) v2(94.16,53.86) v2(94.16,51.32) v2(95.03,43.24) v2(95.03,41.17) v2(95.03,39.1) v2(95.74,105.92) v2(95.74,104.01) v2(95.74,101.47) v2(95.74,98.93) v2(95.74,96.39) v2(95.74,93.85) v2(95.74,92.46) v2(95.74,90.93) v2(95.74,89.53) v2(95.84,43.24) v2(95.84,41.17) v2(95.84,39.1) v2(96.22,8.46) v2(96.22,5.92) v2(96.7,58.94) v2(96.7,56.4) v2(96.7,53.86) v2(96.7,51.32) v2(98.17,19.26) v2(98.17,18.04) v2(98.21,16.17) v2(98.21,15.46) v2(98.28,105.92) v2(98.28,104.01) v2(98.28,101.47) v2(98.28,98.93) v2(98.28,96.39) v2(98.28,93.85) v2(98.28,92.46) v2(98.28,90.93) v2(98.29,21.54) v2(98.29,20.83) v2(98.49,35.74) v2(98.76,8.46) v2(98.76,5.92) v2(98.76,3.38) v2(98.87,19.26) v2(98.87,18.04) v2(99.24,64.02) v2(99.24,61.48) v2(99.24,51.32) v2(99.24,33.54) v2(99.24,31) v2(99.24,28.46) v2(99.24,25.92) v2(99.24,23.38) v2(99.26,21.54) v2(99.26,20.83) v2(99.42,16.17) v2(99.42,15.46) v2(100.67,9.08) v2(100.82,105.92) v2(100.82,104.01) v2(100.82,101.47) v2(100.82,98.93) v2(100.82,96.39) v2(100.82,93.85) v2(101.03,38.21) v2(101.15,58.94) v2(101.27,15.96) v2(101.27,14.92) v2(101.27,13.88) v2(101.78,66.56) v2(101.78,51.32) v2(101.78,48.78) v2(101.78,46.24) v2(101.78,43.7) v2(101.78,41.16) v2(101.78,38.62) v2(101.78,33.54) v2(101.78,31) v2(101.78,25.92) v2(101.78,23.38) v2(102.44,27.7) v2(102.51,15.96) v2(102.51,13.88) v2(102.7,18.01) v2(103.36,105.92) v2(103.36,104.01) v2(103.36,101.47) v2(103.36,98.93) v2(103.36,96.39) v2(103.69,58.94) v2(103.69,56.4) v2(103.69,51.32) v2(103.69,48.78) v2(103.69,46.24) v2(103.69,43.7) v2(103.69,41.16) v2(103.69,38.62) v2(103.76,15.96) v2(103.76,14.92) v2(103.76,13.88) v2(104.32,69.1) v2(104.32,20.84) v2(105.35,10.72) v2(106.23,66.56) v2(106.23,64.02) v2(106.23,61.48) v2(106.23,58.94) v2(106.23,56.4) v2(106.23,53.86) v2(106.23,51.32) v2(106.23,43.7) v2(106.23,41.16) v2(106.23,38.62) v2(106.23,36.08) v2(106.23,33.54) v2(108.18,105.66) v2(108.77,43.7) v2(108.77,41.16) v2(111.31,43.7) v2(111.31,41.16) v2(113.26,105.66) v2(113.85,43.7) v2(113.85,41.16) v2(118.47,101.73) v2(123.55,105.92) v2(123.55,101.73) v2(125.07,45.72) v2(125.07,40.64) v2(126.19,76.83) v2(127.13,77.77) v2(127.11,72.64) v2(127.36,105.92) v2(127.74,96.27) v2(128.07,78.71) v2(128.2,91.82) v2(129.09,89.31) v2(129.09,86.36) v2(129.09,83.57) v2(129.09,80.77) v2(129.52,74.17) v2(131.42,106.17) v2(131.42,101.85) v2(131.42,96.77) v2(131.42,91.69) v2(131.42,86.61) v2(131.42,81.53) v2(131.42,76.33) v2(131.42,71.25) v2(131.42,66.17) v2(131.42,61.09) v2(131.42,56.01) v2(131.42,50.93) v2(131.42,45.85) v2(131.42,40.77) v3(60.12,74.56) v3(60.12,73.61) v3(60.12,72.65) v3(60.12,71.7) v3(60.12,70.75) v3(60.12,69.79) v3(60.12,68.84) v3(61.07,74.56) v3(61.07,73.61) v3(61.07,72.65) v3(61.07,71.7) v3(61.07,70.75) v3(61.07,69.79) v3(61.07,68.84) v3(62.03,74.56) v3(62.03,73.61) v3(62.03,72.65) v3(62.03,71.7) v3(62.03,70.75) v3(62.03,69.79) v3(62.03,68.84) v3(62.98,74.56) v3(62.98,73.61) v3(62.98,72.65) v3(62.98,71.7) v3(62.98,70.75) v3(62.98,69.79) v3(62.98,68.84) v3(63.94,74.56) v3(63.94,73.61) v3(63.94,72.65) v3(63.94,71.7) v3(63.94,70.75) v3(63.94,69.79) v3(63.94,68.84) v3(64.89,74.56) v3(64.89,73.61) v3(64.89,72.65) v3(64.89,71.7) v3(64.89,70.75) v3(64.89,69.79) v3(65.84,74.56) v3(65.84,73.61) v3(65.84,72.65) v3(65.84,71.7) v3(65.84,70.75)
GND2: length 12.9
  TOP w0.381: v2(39.3,7.15) 38.77,7.15 USB.5 38.77,8.89 v2(39.3,8.89) ; v2(37.83,12.36) C186.2 C185.2 ; C187.2 35.11,13.9 v2(35.11,13.53)
  BOTTOM w0.381: C183.2 33.16,10.5 v2(33.16,10.86) 33.19,10.89 U6.21 ; U6.26 29.94,13.22 v2(30.26,13.54) 30.59,13.21 U6.25 ; v2(30.65,22.41) C184.2 ; U6.18 35.14,13.5 v2(35.11,13.53) ; U6.7 v2(32.54,17.76)
  vias: v2(2.28,22.91) v2(4.45,22.78) v2(4.45,22.08) v2(4.82,20.37) v2(4.82,17.83) v2(4.82,15.29) v2(4.82,12.75) v2(4.82,10.21) v2(5.47,22.78) v2(5.47,22.08) v2(7.36,22.91) v2(7.36,20.37) v2(7.36,17.83) v2(7.36,15.29) v2(7.36,12.75) v2(7.36,10.21) v2(9.9,22.91) v2(9.9,20.37) v2(9.9,17.83) v2(9.9,15.29) v2(9.9,12.75) v2(9.9,10.21) v2(9.9,7.67) v2(12.44,22.91) v2(12.44,20.37) v2(12.44,17.83) v2(12.44,15.29) v2(12.44,12.75) v2(12.44,10.21) v2(12.44,7.67) v2(14.98,22.91) v2(14.98,20.37) v2(14.98,17.83) v2(14.98,12.75) v2(14.98,10.21) v2(14.98,7.67) v2(16.39,12.75) v2(17.33,11.35) v2(17.52,22.91) v2(17.52,20.37) v2(17.52,17.83) v2(17.52,15.29) v2(17.52,7.67) v2(17.52,5.13) v2(17.52,2.59) v2(18.75,10.81) v2(18.75,9.6) v2(20.06,22.91) v2(20.06,20.37) v2(20.06,17.83) v2(20.06,5.13) v2(20.06,2.59) v2(20.73,10.81) v2(20.73,9.6) v2(21.9,10.94) v2(21.9,10.23) v2(21.98,16.31) v2(21.98,15.6) v2(22.6,22.91) v2(22.6,20.37) v2(22.6,17.83) v2(22.6,12.75) v2(22.6,2.59) v2(22.69,16.31) v2(22.69,15.6) v2(23.11,10.94) v2(23.11,10.23) v2(25.14,22.91) v2(25.14,20.37) v2(25.14,17.83) v2(25.14,12.75) v2(25.06,9.03) v2(25.14,7.67) v2(25.14,5.13) v2(25.14,2.59) v2(26.27,10.03) v2(26.27,9.27) v2(27.68,22.91) v2(27.68,17.83) v2(27.68,7.67) v2(27.68,5.13) v2(27.68,2.59) v2(29.12,22.92) v2(29.27,14.15) v2(30.22,7.67) v2(30.22,5.13) v2(30.22,2.59) v2(31.25,14.15) v2(31.86,15.32) v2(32.01,8.86) v2(32.01,6.98) v2(32.01,3.36) v2(32.01,1.48) v2(33.42,8.86) v2(33.42,6.98) v2(33.42,3.36) v2(33.42,1.48) v2(33.76,15.32) v2(34.43,22.92) v2(36.3,15.32) v2(36.71,2.59) v2(38.84,17.86) v2(38.84,15.32) v2(38.84,12.78) v2(38.84,10.24) v2(40.91,8.86) v2(40.91,6.98) v2(40.91,3.36) v2(40.91,1.48) v2(41.38,17.86) v2(41.38,15.32) v2(41.38,12.78) v2(41.38,10.24) v2(42.32,8.86) v2(42.32,6.98) v2(42.32,3.36) v2(42.32,1.48) v2(43.49,22.91) v2(43.92,17.86) v2(43.92,15.32) v2(43.92,12.78) v2(43.92,10.24) v2(43.92,7.7) v2(43.92,5.16) v2(43.92,2.62)
ADC_VCMA: length 10.5
  TOP w0.295: U12.1 58.48,74.94
  TOP w0.305: C114.1 58.24,75.18 58.48,74.94
  TOP w0.381: v1(57.13,75.79) 56.85,75.51 C114.1
  BOTTOM w0.381: v1(57.13,75.79) 57.51,75.41 C115.1 54.32,75.06 53.95,74.69 ; 53.95,74.69 R16.2 ; 53.95,74.69 C116.1
ADC_VCMB: length 10.8
  TOP w0.295: 58.37,68.33 58.49,68.44 U12.14
  TOP w0.305: 58.37,68.33 C117.1
  TOP w0.381: C117.1 56.75,67.89 v1(57.05,67.59)
  BOTTOM w0.381: 57.41,68.33 57.41,67.94 v1(57.05,67.59) ; 57.41,68.33 C118.1 ; 57.41,68.33 54.33,68.33 53.95,68.7 ; 53.95,68.7 R27.2 ; 53.95,68.7 C119.1
ADC_VINA+: length 1.7
  TOP w0.203: R12.1 57.61,73.44 U12.4
ADC_VINA-: length 1.7
  TOP w0.203: U12.5 57.6,72.94 R13.1
ADC_VINB+: length 1.5
  TOP w0.203: R25.1 58.56,69.95 58.57,69.94 U12.11
ADC_VINB-: length 1.5
  TOP w0.203: U12.10 57.83,70.44 R24.1
CLK_VIN+: length 1.3
  TOP w0.203: R72.2 v1(60.46,54.15)
  BOTTOM w0.203: v1(60.46,54.15) R76.2
CLK_VIN-: length 1.3
  TOP w0.203: R73.2 v1(61.48,54.15)
  BOTTOM w0.203: v1(61.48,54.15) R77.2
CLKIN+: length 13.3
  TOP w0.203: C108.2 60.77,55.17 60.77,67.24 60.72,67.28 U12.17
CLKIN-: length 13.3
  TOP w0.203: U12.18 61.22,67.28 61.17,67.24 61.17,55.17 C109.2
CLKOUT2+: length 23.8
  TOP w0.203: v1(76.11,41.38) 76.3,41.19 76.58,41.19 77.21,41.82 78.67,41.82 78.72,41.87 U13.15
  BOTTOM w0.203: C173.1 61.15,51.13 61.15,50.57 70.6,41.12 75.29,41.12 75.47,41.3 75.47,41.56 75.66,41.75 75.92,41.75 76.11,41.56 v1(76.11,41.38)
CLKOUT2-: length 23.8
  TOP w0.203: U13.16 78.72,41.36 78.67,41.41 77.37,41.41 76.74,40.78 76.27,40.78 v1(76.11,40.62)
  BOTTOM w0.203: v1(76.11,40.62) 76,40.72 70.43,40.72 60.74,50.4 60.74,51.18 C172.1
CLKOUT3+: length 24.3
  TOP w0.203: v1(76.11,43.61) 76.27,43.45 76.74,43.45 77.37,42.82 78.67,42.82 78.71,42.86 U13.13
  BOTTOM w0.203: C171.1 64.15,51.84 64.15,51.28 64.48,50.95 68.19,50.95 68.62,50.52 68.62,49.28 68.19,48.85 67.47,48.85 67.14,48.52 67.14,47.86 71.64,43.36 75.33,43.36 75.47,43.5 75.47,43.79 75.66,43.98 75.94,43.98 76.11,43.81 v1(76.11,43.61)
CLKOUT3-: length 24.3
  TOP w0.203: v1(76.11,42.85) 76.3,43.04 76.58,43.04 77.21,42.41 78.67,42.41 78.71,42.37 U13.14
  BOTTOM w0.203: C170.1 63.74,51.89 63.74,51.11 64.31,50.55 68.02,50.55 68.22,50.35 68.22,49.45 68.02,49.26 67.3,49.26 66.74,48.69 66.74,47.69 71.47,42.95 76,42.95 v1(76.11,42.85)
CLKOUT4+: length 1.8
  TOP w0.203: U13.24 83.15,40.43 83.2,40.38 83.2,39.23 C166.1
CLKOUT4-: length 1.8
  TOP w0.203: C165.1 83.61,39.23 83.61,40.38 83.66,40.43 U13.25
CSB_ADC: length 28.3
  TOP w0.203: v2(29.88,25.65) v2(29.88,28.18)
  BOTTOM w0.203: v2(29.88,28.18) 35.21,28.18 37.57,25.83 37.57,24.87 38.18,24.26 41.18,24.26 45.11,28.18 U14.13 ; v2(29.88,25.65) v1(29.88,21.93)
CSB_ADC_3P0: length 29.1
  TOP w0.203: v2(60.72,91.95) v2(60.72,80.01) ; U12.54 v1(60.72,76.45)
  BOTTOM w0.203: R66.2 J3.2 62.21,91.95 v2(60.72,91.95) R135.2 ; v1(60.72,76.45) v2(60.72,80.01)
CSB_LMH: length 21.7
  BOTTOM w0.203: U15.13 21.78,27.32 22.81,26.29 34.4,26.29 35.19,25.5 v1(35.19,21.98)
CSB_LMH_3P3: length 34.2
  L4_POWER w0.203: J1.2 21.78,54.68 11.58,64.87 v2(11.58,67.61)
  BOTTOM w0.203: R139.2 J1.2
  BOTTOM w0.254: v2(11.58,67.61) 11.58,67.92 12.49,68.83 U3.32
CSB_LMK: length 25.6
  TOP w0.203: v2(49.35,21.73) 46.89,19.27 29.27,19.27 28.52,20.02 28.52,21.33 v1(29.12,21.93)
  BOTTOM w0.203: U16.13 v2(49.35,21.73)
CSB_LMK_3P3: length 44.7
  TOP w0.203: U13.18 80.15,39.67 77.73,37.24 77.73,22.41 76.67,21.35 v2(67.92,21.35)
  BOTTOM w0.203: R146.1 R147.1 v2(67.92,21.35) 60.73,21.35 J2.2 R142.2
DIR_LMK: length 17.2
  TOP w0.203: v1(32.17,21.93) 33.92,20.18 v2(46.79,20.18)
  BOTTOM w0.203: U16.11 47.04,20.43 v2(46.79,20.18) R125.2
EXT_ ADC_CLK: length 58.5
  TOP w0.33: R219.1 v1(55.63,9.27)
  BOTTOM w0.33: v1(88.7,35.71) 88.65,35.76 85.67,35.76 85.01,35.1 82.22,35.1 81.1,33.99 81.1,10.95 79.88,9.73 56.08,9.73 v1(55.63,9.27)
EXTREF_XO: length 5.8
  TOP w0.33: R109.2 C159.1 R108.2 89.73,35.73 R234.1
FILT_VINA+: length 3.7
  BOTTOM w0.203: 28.19,78.26 L9.1 ; 28.19,78.26 28.93,78.26 C48.2 29.76,78.34 C16.2 C47.2 ; 28.19,78.26 C31.1
FILT_VINA-: length 3.7
  BOTTOM w0.203: C46.2 C15.1 29.76,77.32 C48.1 28.93,77.4 28.19,77.4 ; C30.1 28.19,77.4 ; 28.19,77.4 L9.2
FILT_VINB+: length 3.7
  BOTTOM w0.203: C40.2 C13.1 29.76,65.05 C42.1 28.93,65.13 28.19,65.13 ; C28.1 28.19,65.13 ; 28.19,65.13 L5.2
FILT_VINB-: length 3.7
  BOTTOM w0.203: 28.19,65.99 L5.1 ; 28.19,65.99 28.93,65.99 C42.2 29.76,66.07 C14.2 C41.2 ; 28.19,65.99 C29.1
FILT_VOUTA+: length 21.5
  BOTTOM w0.203: C49.2 32.99,78.26 L12.1 ; C49.2 32.99,78.41 L11.2 ; C49.2 C51.2 33.91,78.53 34.48,79.1 35.35,79.1 36.41,78.03 43.14,78.03 46.32,74.85 49.67,74.85 R14.2
FILT_VOUTA-: length 21.5
  BOTTOM w0.203: C49.1 C50.1 33.91,77.13 34.48,76.56 35.35,76.56 36.41,77.62 42.97,77.62 46.15,74.45 49.67,74.45 R15.2 ; C49.1 32.99,77.24 L10.2 ; C49.1 32.99,77.4 L12.2
FILT_VOUTB+: length 21.4
  BOTTOM w0.203: C43.1 C44.1 33.91,64.86 34.48,64.29 35.35,64.29 36.41,65.36 43.14,65.36 46.27,68.49 49.65,68.49 R29.1 ; C43.1 32.99,65.13 L8.2 ; C43.1 32.99,64.98 L6.2
FILT_VOUTB-: length 21.4
  BOTTOM w0.203: C43.2 32.99,66.14 L7.2 ; C43.2 C45.2 33.91,66.26 34.48,66.83 35.35,66.83 36.41,65.76 42.97,65.76 46.11,68.9 49.66,68.9 R28.1 ; C43.2 32.99,65.99 L8.1
FMC_ADC_DEVCLK+: length 78.6
  L3_POWER w0.203: v1(105.92,88.19) 106.02,88.09 119.18,88.09 v1(119.61,88.52)
  BOTTOM w0.203: R76.1 60.77,56.13 60.77,61.34 63.77,64.34 63.77,67.59 68.14,71.96 88.97,71.96 105.09,88.09 105.82,88.09 v1(105.92,88.19) ; FMC.D8 v1(119.61,88.52)
